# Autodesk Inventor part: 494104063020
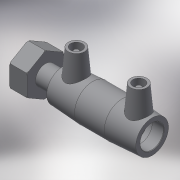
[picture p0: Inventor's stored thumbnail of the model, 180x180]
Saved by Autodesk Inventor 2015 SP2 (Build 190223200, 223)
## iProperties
Created: 2017-06
Part Number: 494104063020
Material: Generic
Description: PLASSON FEMALE FREE NUT TRANSITION COUPLER 63-2"
Document SubType Name: Modeling
Designer: KIM
Mass: 55.0731 g
Surface Area: 148.067 cm^2
Volume: 55.0731 cm^3
Density: 1 g/cm^3
Appearance: Default
Author: KIM
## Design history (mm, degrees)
derived "494104.ipt"
feature "Solid1::494104.ipt"
tag "TaggingFeature1"
body "Solid1"
other parameters: "d0" = 117, "d1" = 63, "d2" = 82, "d3" = 57, "d4" = 39, "d5" = 73.8, "d6" = 59.85, "d7" = 63, "d8" = 168 deg, "d10" = 22.8, "d11" = 7.6, "d29" = 57, "d30" = 14, "d31" = 40.95, "d34" = 5 deg, "d41" = 4, "d42" = 14, "d43" = 0, "d48" = 3, "d49" = 0, "d55" = 44, "d57" = 38, "d80" = 1.26, "d83" = 22, "d84" = 14.52, "d85" = 1.452, "d86" = 45.3248, "d87" = 56.656, "d88" = 84.984, "d89" = 82, "d90" = 1.69968, "d94" = 0, "d95" = 1.452, "d96" = 39.6592, "d_" = 63, "L_" = 161, "L_1" = 57, "D_1" = 82, "A_" = 57, "d_2" = 12, "L_2" = 44, "D_" = 38, "G_" = 56.656
